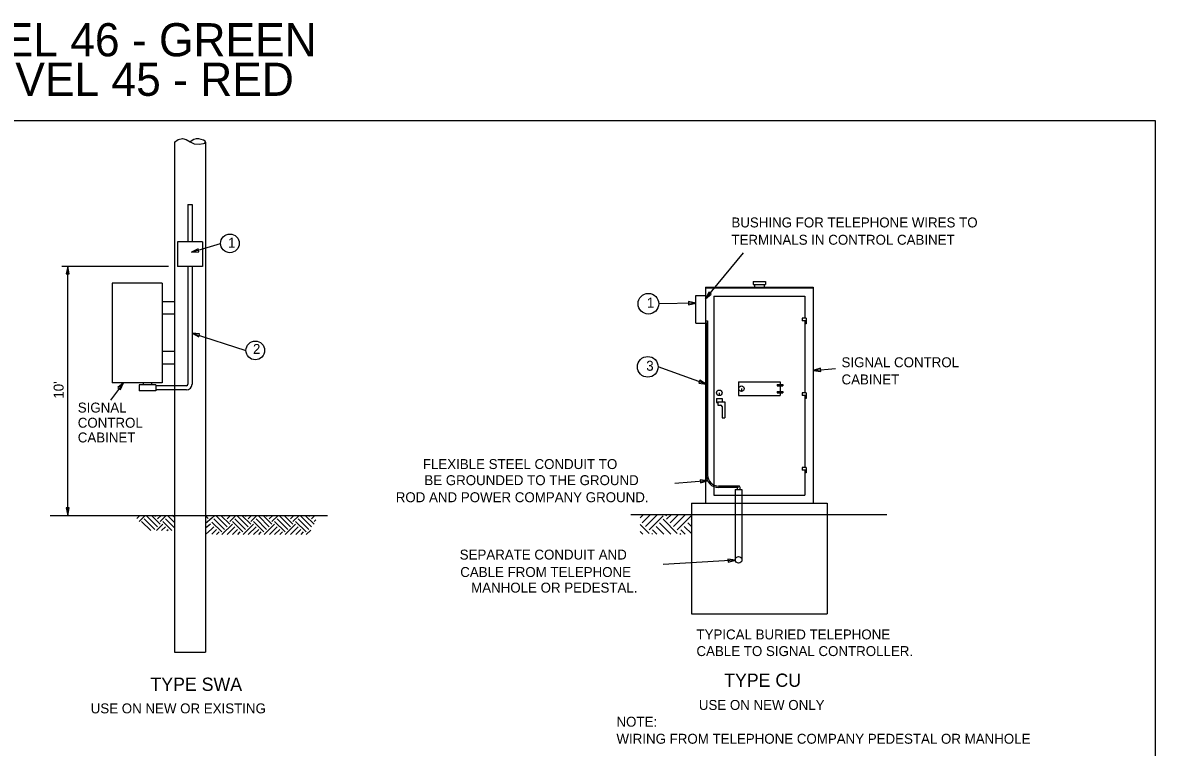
# Model space of a CAD drawing. Extents: x -439.1 to -407.9, y -458.1 to -436.2.
# Drawn here: x -424.94 to -407.86, y -447.12 to -436.2 of the extents above; entities that cross this region are included whole.
import ezdxf

# ---------------------------------------------------------------- set-up
doc = ezdxf.new("R2010")
doc.units = 0
for name, color, linetype in [('Draft_Named_Boundary', 7, 'Continuous'), ('Level 4', 7, 'Continuous'), ('Level 45', 7, 'Continuous'), ('Level 46', 7, 'Continuous')]:
    doc.layers.add(name, color=color, linetype=linetype)

msp = doc.modelspace()

# ---------------------------------------------------------------- linework, layer by layer
at = {"layer": 'Draft_Named_Boundary'}
msp.add_lwpolyline([(-439.109, -458.051), (-407.859, -458.051), (-407.859, -437.676), (-439.109, -437.676)], close=True, dxfattribs=at)
at = {"layer": 'Level 4'}
for p, q in [((-422.647, -438.001), (-422.647, -443.626)), ((-422.178, -438.001), (-422.178, -443.626)), ((-422.444, -438.938), (-422.381, -438.938)), ((-422.444, -438.938), (-422.444, -439.501)), ((-422.381, -438.938), (-422.381, -439.501)), ((-422.6, -439.501), (-422.6, -439.876)), ((-422.225, -439.501), (-422.6, -439.501)), ((-422.39, -439.657), (-421.95, -439.525)), ((-422.225, -439.501), (-422.225, -439.876)), ((-414.641, -440.363), (-414.069, -439.666)), ((-422.734, -439.876), (-424.346, -439.876)), ((-424.255, -443.626), (-424.255, -439.876)), ((-422.225, -439.876), (-422.6, -439.876)), ((-422.444, -439.876), (-422.444, -441.649)), ((-422.381, -439.876), (-422.381, -441.649)), ((-423.584, -440.126), (-423.584, -441.626)), ((-422.834, -440.126), (-423.584, -440.126)), ((-422.834, -440.126), (-422.834, -441.626)), ((-414.641, -440.185), (-414.641, -443.445)), ((-414.641, -440.185), (-413.016, -440.185)), ((-414.641, -440.195), (-413.016, -440.195)), ((-413.923, -440.102), (-413.735, -440.102)), ((-413.923, -440.102), (-413.923, -440.143)), ((-413.923, -440.143), (-413.735, -440.143)), ((-413.902, -440.143), (-413.902, -440.185)), ((-413.756, -440.143), (-413.756, -440.185)), ((-413.735, -440.102), (-413.735, -440.143)), ((-413.016, -440.185), (-413.016, -443.445)), ((-414.787, -440.727), (-414.787, -440.31)), ((-414.787, -440.31), (-414.641, -440.31)), ((-414.516, -440.32), (-414.516, -443.32)), ((-414.516, -440.32), (-413.141, -440.32)), ((-413.141, -440.32), (-413.141, -440.654)), ((-422.647, -440.407), (-422.834, -440.407)), ((-414.787, -440.426), (-415.346, -440.435)), ((-422.647, -440.595), (-422.834, -440.595)), ((-414.787, -440.727), (-414.641, -440.727)), ((-414.641, -440.695), (-414.61, -440.695)), ((-414.641, -440.716), (-414.631, -440.716)), ((-414.631, -440.716), (-414.631, -443.018)), ((-414.61, -440.695), (-414.61, -443.018)), ((-413.183, -440.654), (-413.183, -440.695)), ((-413.121, -440.654), (-413.183, -440.654)), ((-413.121, -440.695), (-413.183, -440.695)), ((-413.141, -440.695), (-413.141, -441.779)), ((-413.121, -440.654), (-413.121, -440.737)), ((-422.381, -440.881), (-421.568, -441.139)), ((-413.121, -440.737), (-413.141, -440.737)), ((-422.647, -441.157), (-422.834, -441.157)), ((-422.647, -441.345), (-422.834, -441.345)), ((-414.631, -441.647), (-415.355, -441.387)), ((-413.016, -441.441), (-412.682, -441.414)), ((-423.414, -441.626), (-423.613, -441.891)), ((-422.834, -441.626), (-423.584, -441.626)), ((-422.928, -441.657), (-423.178, -441.657)), ((-423.178, -441.657), (-423.178, -441.751)), ((-422.928, -441.751), (-423.178, -441.751)), ((-423.116, -441.626), (-423.116, -441.657)), ((-422.991, -441.626), (-422.991, -441.657)), ((-422.928, -441.657), (-422.928, -441.751)), ((-422.467, -441.673), (-422.928, -441.673)), ((-422.467, -441.735), (-422.928, -441.735)), ((-414.141, -441.612), (-413.516, -441.612)), ((-414.141, -441.612), (-414.141, -441.82)), ((-414.1, -441.716), (-414.1, -441.758)), ((-413.558, -441.654), (-413.475, -441.654)), ((-413.558, -441.654), (-413.558, -441.675)), ((-413.558, -441.675), (-413.475, -441.675)), ((-413.516, -441.612), (-413.516, -441.654)), ((-413.516, -441.675), (-413.516, -441.758)), ((-413.475, -441.654), (-413.475, -441.675)), ((-414.475, -441.862), (-414.475, -441.925)), ((-414.475, -441.862), (-414.391, -441.862)), ((-414.475, -441.925), (-414.454, -441.925)), ((-414.454, -441.914), (-414.454, -441.966)), ((-414.454, -441.914), (-414.35, -441.914)), ((-414.433, -441.779), (-414.433, -441.82)), ((-414.391, -441.862), (-414.391, -441.914)), ((-414.35, -441.914), (-414.35, -442.154)), ((-414.141, -441.82), (-413.516, -441.82)), ((-413.558, -441.758), (-413.475, -441.758)), ((-413.558, -441.758), (-413.558, -441.779)), ((-413.558, -441.779), (-413.475, -441.779)), ((-413.516, -441.779), (-413.516, -441.82)), ((-413.475, -441.758), (-413.475, -441.779)), ((-413.183, -441.779), (-413.183, -441.82)), ((-413.121, -441.779), (-413.183, -441.779)), ((-413.121, -441.82), (-413.183, -441.82)), ((-413.141, -441.82), (-413.141, -442.904)), ((-413.121, -441.862), (-413.141, -441.862)), ((-413.121, -441.779), (-413.121, -441.862)), ((-414.454, -441.966), (-414.412, -441.966)), ((-414.391, -441.987), (-414.391, -442.154)), ((-414.391, -442.154), (-414.35, -442.154)), ((-413.183, -442.904), (-413.183, -442.945)), ((-413.121, -442.904), (-413.183, -442.904)), ((-413.121, -442.945), (-413.183, -442.945)), ((-413.141, -442.945), (-413.141, -443.32)), ((-413.121, -442.904), (-413.121, -442.987)), ((-414.61, -443.104), (-415.102, -443.144)), ((-413.121, -442.987), (-413.141, -442.987)), ((-414.141, -443.185), (-414.443, -443.185)), ((-414.141, -443.206), (-414.443, -443.206)), ((-414.191, -443.237), (-414.092, -443.237)), ((-414.191, -443.237), (-414.191, -444.297)), ((-414.162, -443.206), (-414.162, -443.237)), ((-414.121, -443.206), (-414.121, -443.237)), ((-414.092, -443.237), (-414.092, -444.297)), ((-414.85, -443.445), (-412.808, -443.445)), ((-414.85, -443.445), (-414.85, -443.612)), ((-414.516, -443.32), (-413.141, -443.32)), ((-412.808, -443.445), (-412.808, -443.612)), ((-424.522, -443.626), (-420.34, -443.626)), ((-423.216, -443.674), (-423.168, -443.626)), ((-423.181, -443.718), (-423.088, -443.626)), ((-422.863, -443.758), (-422.995, -443.626)), ((-422.942, -443.639), (-422.929, -443.626)), ((-422.902, -443.679), (-422.849, -443.626)), ((-422.863, -443.718), (-422.77, -443.626)), ((-422.647, -443.656), (-422.677, -443.626)), ((-422.647, -443.626), (-422.647, -445.688)), ((-422.178, -443.626), (-422.178, -445.688)), ((-422.137, -443.675), (-422.177, -443.629)), ((-422.084, -443.67), (-422.04, -443.626)), ((-421.814, -443.758), (-421.947, -443.626)), ((-421.894, -443.639), (-421.881, -443.626)), ((-421.854, -443.679), (-421.801, -443.626)), ((-421.814, -443.718), (-421.722, -443.626)), ((-421.496, -443.758), (-421.629, -443.626)), ((-421.576, -443.639), (-421.562, -443.626)), ((-421.536, -443.679), (-421.483, -443.626)), ((-421.496, -443.718), (-421.403, -443.626)), ((-421.178, -443.758), (-421.31, -443.626)), ((-421.257, -443.639), (-421.244, -443.626)), ((-421.218, -443.679), (-421.165, -443.626)), ((-421.178, -443.718), (-421.085, -443.626)), ((-420.86, -443.758), (-420.992, -443.626)), ((-420.939, -443.639), (-420.926, -443.626)), ((-420.899, -443.679), (-420.847, -443.626)), ((-420.86, -443.718), (-420.767, -443.626)), ((-420.541, -443.758), (-420.674, -443.626)), ((-420.621, -443.639), (-420.608, -443.626)), ((-420.581, -443.679), (-420.528, -443.626)), ((-415.768, -443.612), (-411.908, -443.612)), ((-415.627, -443.662), (-415.577, -443.612)), ((-415.598, -443.739), (-415.471, -443.612)), ((-415.545, -443.792), (-415.365, -443.612)), ((-415.492, -443.845), (-415.28, -443.633)), ((-415.227, -443.633), (-415.248, -443.612)), ((-415.227, -443.686), (-415.153, -443.612)), ((-415.174, -443.739), (-415.047, -443.612)), ((-415.121, -443.792), (-414.941, -443.612)), ((-415.068, -443.845), (-414.856, -443.633)), ((-414.85, -443.612), (-414.85, -445.112)), ((-412.808, -443.612), (-412.808, -445.112)), ((-423.005, -443.855), (-423.141, -443.718)), ((-422.942, -443.838), (-423.101, -443.679)), ((-422.902, -443.798), (-423.061, -443.639)), ((-422.919, -443.855), (-422.823, -443.758)), ((-422.84, -443.855), (-422.783, -443.798)), ((-422.687, -443.855), (-422.823, -443.718)), ((-422.647, -443.815), (-422.783, -443.679)), ((-422.647, -443.736), (-422.743, -443.639)), ((-422.084, -443.67), (-422.177, -443.748)), ((-422.104, -443.761), (-422.177, -443.82)), ((-421.934, -443.877), (-422.084, -443.727)), ((-422.084, -443.829), (-422.053, -443.798)), ((-421.894, -443.838), (-422.053, -443.679)), ((-421.854, -443.798), (-422.013, -443.639)), ((-421.932, -443.915), (-421.774, -443.758)), ((-421.852, -443.915), (-421.735, -443.798)), ((-421.615, -443.877), (-421.774, -443.718)), ((-421.576, -443.838), (-421.735, -443.679)), ((-421.536, -443.798), (-421.695, -443.639)), ((-421.613, -443.915), (-421.456, -443.758)), ((-421.534, -443.915), (-421.417, -443.798)), ((-421.297, -443.877), (-421.456, -443.718)), ((-421.257, -443.838), (-421.417, -443.679)), ((-421.218, -443.798), (-421.377, -443.639)), ((-421.295, -443.915), (-421.138, -443.758)), ((-421.216, -443.915), (-421.098, -443.798)), ((-420.979, -443.877), (-421.138, -443.718)), ((-420.939, -443.838), (-421.098, -443.679)), ((-420.899, -443.798), (-421.059, -443.639)), ((-420.977, -443.915), (-420.82, -443.758)), ((-420.897, -443.915), (-420.78, -443.798)), ((-420.661, -443.877), (-420.82, -443.718)), ((-420.621, -443.838), (-420.78, -443.679)), ((-420.581, -443.798), (-420.74, -443.639)), ((-420.541, -443.718), (-420.515, -443.692)), ((-415.492, -443.898), (-415.627, -443.764)), ((-415.268, -443.911), (-415.386, -443.792)), ((-415.162, -443.911), (-415.333, -443.739)), ((-415.068, -443.898), (-415.28, -443.686)), ((-414.849, -443.905), (-414.962, -443.792)), ((-414.849, -443.799), (-414.909, -443.739)), ((-414.849, -443.693), (-414.856, -443.686)), ((-422.76, -443.855), (-422.743, -443.838)), ((-422.084, -443.829), (-422.177, -443.913)), ((-422.084, -443.909), (-422.013, -443.838)), ((-422.011, -443.915), (-421.973, -443.877)), ((-421.772, -443.915), (-421.695, -443.838)), ((-421.693, -443.915), (-421.655, -443.877)), ((-421.454, -443.915), (-421.377, -443.838)), ((-421.375, -443.915), (-421.337, -443.877)), ((-421.136, -443.915), (-421.059, -443.838)), ((-421.057, -443.915), (-421.019, -443.877)), ((-420.818, -443.915), (-420.74, -443.838)), ((-420.738, -443.915), (-420.701, -443.877)), ((-420.659, -443.915), (-420.592, -443.848)), ((-415.586, -443.911), (-415.627, -443.87)), ((-415.452, -443.911), (-415.439, -443.898)), ((-415.374, -443.911), (-415.439, -443.845)), ((-415.027, -443.911), (-415.015, -443.898)), ((-414.949, -443.911), (-415.015, -443.845)), ((-414.19, -444.302), (-415.278, -444.368)), ((-414.85, -445.112), (-412.808, -445.112)), ((-422.647, -445.688), (-422.178, -445.688))]:
    msp.add_line(p, q, dxfattribs=at)
msp.add_lwpolyline([(-422.647, -438.001), (-422.591, -437.96), (-422.527, -437.943), (-422.468, -437.961), (-422.411, -437.994), (-422.348, -438.023), (-422.273, -438.03), (-422.211, -438.021), (-422.188, -438.012), (-422.178, -438.001), (-422.186, -437.986), (-422.21, -437.971), (-422.28, -437.95), (-422.319, -437.95), (-422.353, -437.959), (-422.411, -437.994)], dxfattribs=at)
for points in [[(-422.288, -439.608), (-422.39, -439.657), (-422.277, -439.652)], [(-424.232, -439.986), (-424.255, -439.876), (-424.278, -439.986)], [(-414.588, -440.263), (-414.641, -440.363), (-414.553, -440.292)], [(-414.897, -440.45), (-414.787, -440.426), (-414.898, -440.404)], [(-422.268, -440.891), (-422.381, -440.881), (-422.281, -440.935)], [(-412.907, -441.409), (-413.016, -441.441), (-412.904, -441.455)], [(-423.462, -441.728), (-423.414, -441.626), (-423.499, -441.701)], [(-414.743, -441.633), (-414.631, -441.647), (-414.728, -441.59)], [(-414.718, -443.136), (-414.61, -443.104), (-414.722, -443.091)], [(-424.278, -443.515), (-424.255, -443.626), (-424.232, -443.515)], [(-414.299, -444.331), (-414.19, -444.302), (-414.302, -444.286)]]:
    msp.add_lwpolyline(points, close=True, dxfattribs=at)
for centre, radius in [((-421.81, -439.525), 0.141), ((-415.502, -440.435), 0.156), ((-421.428, -441.139), 0.141), ((-415.511, -441.387), 0.156), ((-414.433, -441.779), 0.0417), ((-414.099, -441.716), 0.0417), ((-414.141, -444.297), 0.0495)]:
    msp.add_circle(centre, radius, dxfattribs=at)
for centre, radius, start, end in [((-422.467, -441.649), 0.0234, 270, 0), ((-422.467, -441.649), 0.0859, 270, 0), ((-414.412, -441.987), 0.0208, 0, 90), ((-414.443, -443.018), 0.188, 180, 270), ((-414.443, -443.018), 0.167, 180, 270), ((-414.141, -443.206), 0.0208, 0, 180.0009)]:
    msp.add_arc(centre, radius, start, end, dxfattribs=at)

# ---------------------------------------------------------------- texts
for s, height, p in [('BUSHING FOR TELEPHONE WIRES TO ', 0.15, (-414.25, -439.285)), ('1', 0.15, (-421.839, -439.591)), ('TERMINALS IN CONTROL CABINET', 0.15, (-414.25, -439.546)), ('1', 0.15, (-415.525, -440.495)), ('2', 0.15, (-421.463, -441.192)), ('SIGNAL CONTROL', 0.15, (-412.59, -441.393)), ('3', 0.15, (-415.534, -441.446)), ('CABINET', 0.15, (-412.59, -441.652)), ('SIGNAL', 0.15, (-424.104, -442.076)), ('CONTROL', 0.15, (-424.104, -442.305)), ('CABINET', 0.15, (-424.104, -442.527)), ('FLEXIBLE STEEL CONDUIT TO', 0.15, (-418.902, -442.928)), ('BE GROUNDED TO THE GROUND', 0.15, (-418.879, -443.171)), ('ROD AND POWER COMPANY GROUND.', 0.15, (-419.31, -443.428)), ('SEPARATE CONDUIT AND ', 0.15, (-418.346, -444.293)), ('CABLE FROM TELEPHONE', 0.15, (-418.338, -444.556)), ('MANHOLE OR PEDESTAL.', 0.15, (-418.174, -444.791)), ('TYPICAL BURIED TELEPHONE', 0.15, (-414.777, -445.497)), ('CABLE TO SIGNAL CONTROLLER.', 0.15, (-414.777, -445.748)), ('TYPE CU', 0.2, (-414.36, -446.212)), ('TYPE SWA', 0.2, (-423.009, -446.273)), ('USE ON NEW OR EXISTING', 0.15, (-423.909, -446.612)), ('USE ON NEW ONLY', 0.15, (-414.741, -446.56)), ('NOTE:', 0.15, (-415.983, -446.813)), ('WIRING FROM TELEPHONE COMPANY PEDESTAL OR MANHOLE', 0.15, (-415.983, -447.07))]:
    msp.add_text(s, height=height, dxfattribs=at).set_placement(p)
msp.add_text("10'", height=0.15, rotation=90, dxfattribs=at).set_placement((-424.318, -441.867))
at = {"layer": 'Level 45'}
msp.add_text('ENGLISH - LEVEL 45 - RED', height=0.5, dxfattribs=at).set_placement((-429.393, -437.301))
at = {"layer": 'Level 46'}
msp.add_text('METRIC - LEVEL 46 - GREEN', height=0.5, dxfattribs=at).set_placement((-429.642, -436.705))

doc.saveas('drawing.dxf')
